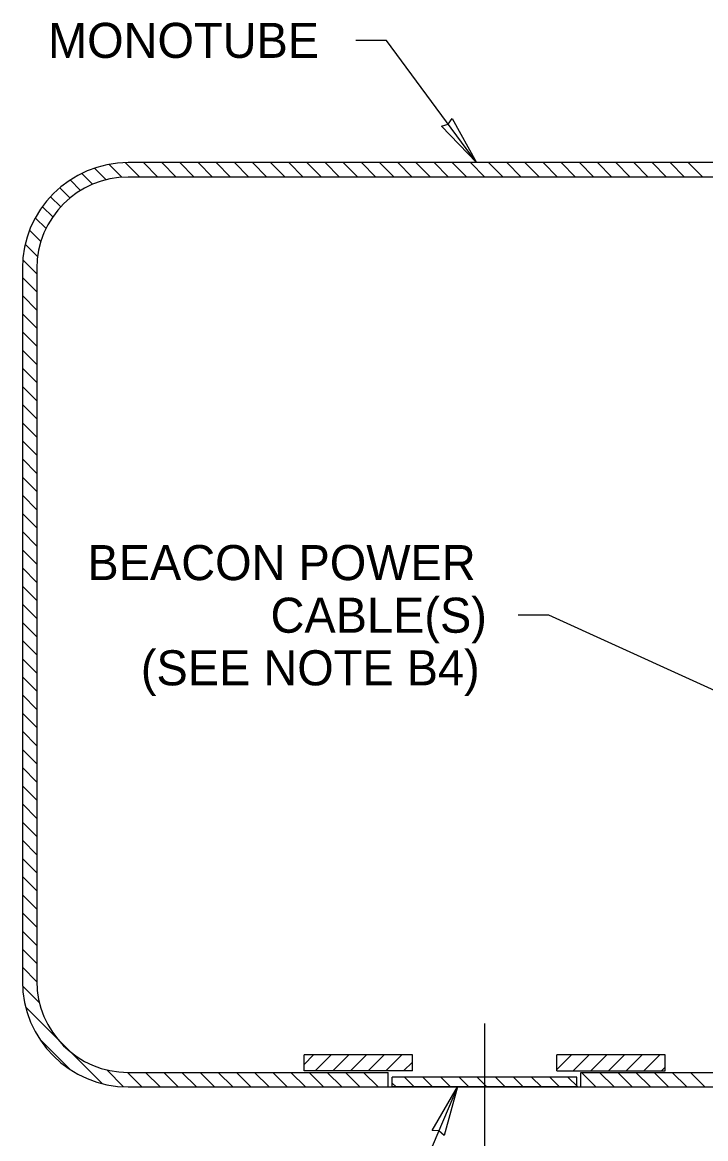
# Model space of a CAD drawing. Extents: x 99862 to 103680, y 99470 to 105076.
# Drawn here: x 100256 to 100568, y 103389 to 103898 of the extents above; entities that cross this region are included whole.
import ezdxf

# ---------------------------------------------------------------- set-up
doc = ezdxf.new("R2010")
doc.units = 0
for name, color, linetype in [('Level 12', 7, 'Continuous'), ('Level 15', 7, 'Continuous'), ('Level 20', 7, 'Continuous')]:
    doc.layers.add(name, color=color, linetype=linetype)

msp = doc.modelspace()

# ---------------------------------------------------------------- linework, layer by layer
at = {"layer": 'Level 12'}
for p, q in [((100289.22, 103831.55), (100294.49, 103826.28)), ((100295.77, 103833.28), (100301.64, 103827.41)), ((100303.29, 103834.04), (100309.82, 103827.51)), ((100629.6, 103834.1), (100304.55, 103834.1)), ((100311.52, 103834.1), (100318.11, 103827.51)), ((100319.8, 103834.1), (100326.39, 103827.51)), ((100328.08, 103834.1), (100334.67, 103827.51)), ((100336.37, 103834.1), (100342.95, 103827.51)), ((100344.65, 103834.1), (100351.24, 103827.51)), ((100352.93, 103834.1), (100359.52, 103827.51)), ((100361.21, 103834.1), (100367.8, 103827.51)), ((100369.5, 103834.1), (100376.09, 103827.51)), ((100377.78, 103834.1), (100384.37, 103827.51)), ((100386.06, 103834.1), (100392.65, 103827.51)), ((100394.35, 103834.1), (100400.93, 103827.51)), ((100402.63, 103834.1), (100409.22, 103827.51)), ((100410.91, 103834.1), (100417.5, 103827.51)), ((100419.19, 103834.1), (100425.78, 103827.51)), ((100427.48, 103834.1), (100434.07, 103827.51)), ((100435.76, 103834.1), (100442.35, 103827.51)), ((100444.04, 103834.1), (100450.63, 103827.51)), ((100452.33, 103834.1), (100458.91, 103827.51)), ((100460.61, 103834.1), (100467.2, 103827.51)), ((100468.89, 103834.1), (100475.48, 103827.51)), ((100477.17, 103834.1), (100483.76, 103827.51)), ((100485.46, 103834.1), (100492.05, 103827.51)), ((100493.74, 103834.1), (100500.33, 103827.51)), ((100502.02, 103834.1), (100508.61, 103827.51)), ((100510.31, 103834.1), (100516.89, 103827.51)), ((100518.59, 103834.1), (100525.18, 103827.51)), ((100526.87, 103834.1), (100533.46, 103827.51)), ((100535.15, 103834.1), (100541.74, 103827.51)), ((100543.44, 103834.1), (100550.03, 103827.51)), ((100551.72, 103834.1), (100558.31, 103827.51)), ((100560, 103834.1), (100566.59, 103827.51)), ((100278.04, 103826.17), (100282.8, 103821.4)), ((100283.34, 103829.15), (100288.28, 103824.21)), ((100629.6, 103827.51), (100304.55, 103827.51)), ((100273.32, 103822.61), (100277.97, 103817.96)), ((100269.1, 103818.54), (100273.72, 103813.92)), ((100265.37, 103813.98), (100270.07, 103809.29)), ((100262.15, 103808.93), (100267.03, 103804.05)), ((100259.54, 103803.25), (100264.68, 103798.11)), ((100257.58, 103796.92), (100263.19, 103791.32)), ((100256.23, 103785.78), (100256.23, 103528.6)), ((100256.43, 103789.8), (100262.82, 103783.41)), ((100262.82, 103785.78), (100262.82, 103528.6)), ((100256.23, 103781.72), (100262.82, 103775.13)), ((100256.23, 103773.43), (100262.82, 103766.84)), ((100256.23, 103765.15), (100262.82, 103758.56)), ((100256.23, 103756.87), (100262.82, 103750.28)), ((100256.23, 103748.59), (100262.82, 103742)), ((100256.23, 103740.3), (100262.82, 103733.71)), ((100256.23, 103732.02), (100262.82, 103725.43)), ((100256.23, 103723.74), (100262.82, 103717.15)), ((100256.23, 103715.45), (100262.82, 103708.87)), ((100256.23, 103707.17), (100262.82, 103700.58)), ((100256.23, 103698.89), (100262.82, 103692.3)), ((100256.23, 103690.61), (100262.82, 103684.02)), ((100256.23, 103682.32), (100262.82, 103675.73)), ((100256.23, 103674.04), (100262.82, 103667.45)), ((100256.23, 103665.76), (100262.82, 103659.17)), ((100256.23, 103657.47), (100262.82, 103650.89)), ((100256.23, 103649.19), (100262.82, 103642.6)), ((100256.23, 103640.91), (100262.82, 103634.32)), ((100256.23, 103632.63), (100262.82, 103626.04)), ((100256.23, 103624.34), (100262.82, 103617.75)), ((100256.23, 103616.06), (100262.82, 103609.47)), ((100256.23, 103607.78), (100262.82, 103601.19)), ((100256.23, 103599.49), (100262.82, 103592.91)), ((100256.23, 103591.21), (100262.82, 103584.62)), ((100256.23, 103582.93), (100262.82, 103576.34)), ((100256.23, 103574.65), (100262.82, 103568.06)), ((100256.23, 103566.36), (100262.82, 103559.77)), ((100256.23, 103558.08), (100262.82, 103551.49)), ((100256.23, 103549.8), (100262.82, 103543.21)), ((100256.23, 103541.51), (100262.82, 103534.93)), ((100256.23, 103533.23), (100262.82, 103526.64)), ((100256.23, 103528.6), (100256.23, 103460.73)), ((100262.82, 103528.6), (100262.82, 103460.73)), ((100256.23, 103524.95), (100262.82, 103518.36)), ((100256.23, 103516.67), (100262.82, 103510.08)), ((100256.23, 103508.38), (100262.82, 103501.79)), ((100256.23, 103500.1), (100262.82, 103493.51)), ((100256.23, 103491.82), (100262.82, 103485.23)), ((100256.23, 103483.53), (100262.82, 103476.95)), ((100256.23, 103475.25), (100262.82, 103468.66)), ((100256.23, 103466.97), (100262.82, 103460.38)), ((100256.33, 103458.59), (100263.98, 103450.93)), ((100257.77, 103448.86), (100292.68, 103413.95)), ((100264.21, 103434.13), (100277.92, 103420.43)), ((100384.71, 103419.73), (100384.71, 103427.05)), ((100434.13, 103427.05), (100384.71, 103427.05)), ((100389.1, 103427.05), (100384.71, 103422.67)), ((100397.15, 103427.05), (100389.83, 103419.73)), ((100405.2, 103427.05), (100397.88, 103419.73)), ((100413.26, 103427.05), (100405.93, 103419.73)), ((100421.31, 103427.05), (100413.99, 103419.73)), ((100429.36, 103427.05), (100422.04, 103419.73)), ((100434.13, 103423.77), (100430.09, 103419.73)), ((100434.13, 103419.73), (100434.13, 103427.05)), ((100500.02, 103419.73), (100500.02, 103427.05)), ((100549.44, 103427.05), (100500.02, 103427.05)), ((100506.72, 103427.05), (100500.02, 103420.35)), ((100514.77, 103427.05), (100507.45, 103419.73)), ((100522.82, 103427.05), (100515.5, 103419.73)), ((100530.88, 103427.05), (100523.56, 103419.73)), ((100538.93, 103427.05), (100531.61, 103419.73)), ((100546.98, 103427.05), (100539.66, 103419.73)), ((100549.44, 103419.73), (100549.44, 103427.05)), ((100294.75, 103420.17), (100302.4, 103412.52)), ((100304.2, 103419), (100310.79, 103412.41)), ((100304.55, 103419), (100423.15, 103419)), ((100312.48, 103419), (100319.07, 103412.41)), ((100320.76, 103419), (100327.35, 103412.41)), ((100329.05, 103419), (100335.63, 103412.41)), ((100337.33, 103419), (100343.92, 103412.41)), ((100345.61, 103419), (100352.2, 103412.41)), ((100353.89, 103419), (100360.48, 103412.41)), ((100362.18, 103419), (100368.77, 103412.41)), ((100370.46, 103419), (100377.05, 103412.41)), ((100378.74, 103419), (100385.33, 103412.41)), ((100434.13, 103419.73), (100384.71, 103419.73)), ((100387.03, 103419), (100393.61, 103412.41)), ((100395.31, 103419), (100401.9, 103412.41)), ((100403.59, 103419), (100410.18, 103412.41)), ((100411.87, 103419), (100418.46, 103412.41)), ((100423.15, 103412.41), (100423.15, 103419)), ((100500.02, 103419.73), (100549.44, 103419.73)), ((100511, 103412.41), (100511, 103419)), ((100511, 103419), (100629.6, 103419)), ((100511.27, 103419), (100517.86, 103412.41)), ((100519.55, 103419), (100526.14, 103412.41)), ((100527.83, 103419), (100534.42, 103412.41)), ((100536.12, 103419), (100542.7, 103412.41)), ((100544.4, 103419), (100550.99, 103412.41)), ((100549.44, 103421.45), (100547.71, 103419.73)), ((100552.68, 103419), (100559.27, 103412.41)), ((100560.96, 103419), (100567.55, 103412.41)), ((100509.17, 103416.87), (100424.98, 103416.87)), ((100424.98, 103412.41), (100424.98, 103416.87)), ((100424.98, 103414.18), (100426.75, 103412.41)), ((100430.57, 103416.87), (100435.03, 103412.41)), ((100438.85, 103416.87), (100443.31, 103412.41)), ((100447.13, 103416.87), (100451.59, 103412.41)), ((100455.41, 103416.87), (100459.88, 103412.41)), ((100463.7, 103416.87), (100468.16, 103412.41)), ((100471.98, 103416.87), (100476.44, 103412.41)), ((100480.26, 103416.87), (100484.73, 103412.41)), ((100488.55, 103416.87), (100493.01, 103412.41)), ((100496.83, 103416.87), (100501.29, 103412.41)), ((100505.11, 103416.87), (100509.57, 103412.41)), ((100509.17, 103412.41), (100509.17, 103416.87)), ((100304.55, 103412.41), (100629.6, 103412.41)), ((100509.17, 103412.41), (100424.98, 103412.41))]:
    msp.add_line(p, q, dxfattribs=at)
for centre, radius, start, end in [((100304.55, 103785.78), 48.32, 90, 180), ((100304.55, 103785.78), 41.73, 90, 180), ((100304.55, 103460.73), 48.32, 180, 270), ((100304.55, 103460.73), 41.73, 180, 270)]:
    msp.add_arc(centre, radius, start, end, dxfattribs=at)
at = {"layer": 'Level 15'}
msp.add_line((100467.07, 103441.33), (100467.07, 103331.47), dxfattribs=at)
for points in [[(100463.45, 103834.1), (100422.39, 103889.86), (100408.39, 103889.86)], [(100590.9, 103584.52), (100496.42, 103627.61), (100482.42, 103627.61)], [(100454.71, 103412.41), (100430.44, 103355.15), (100416.44, 103355.15)]]:
    msp.add_lwpolyline(points, dxfattribs=at)
for points in [[(100463.45, 103834.1), (100447.48, 103850.68), (100450.51, 103851.61), (100452.28, 103854.23)], [(100454.71, 103412.41), (100448.62, 103390.21), (100446.28, 103392.33), (100443.12, 103392.52)]]:
    msp.add_lwpolyline(points, close=True, dxfattribs=at)

# ---------------------------------------------------------------- texts
at = {"layer": 'Level 20'}
for s, p in [('MONOTUBE', (100267.97, 103881.86)), ('BEACON POWER', (100285.9, 103643.61)), ('CABLE(S)', (100369.44, 103619.61)), ('(SEE NOTE B4)', (100310.29, 103595.61))]:
    msp.add_text(s, height=16, dxfattribs=at).set_placement(p)

doc.saveas('drawing.dxf')
